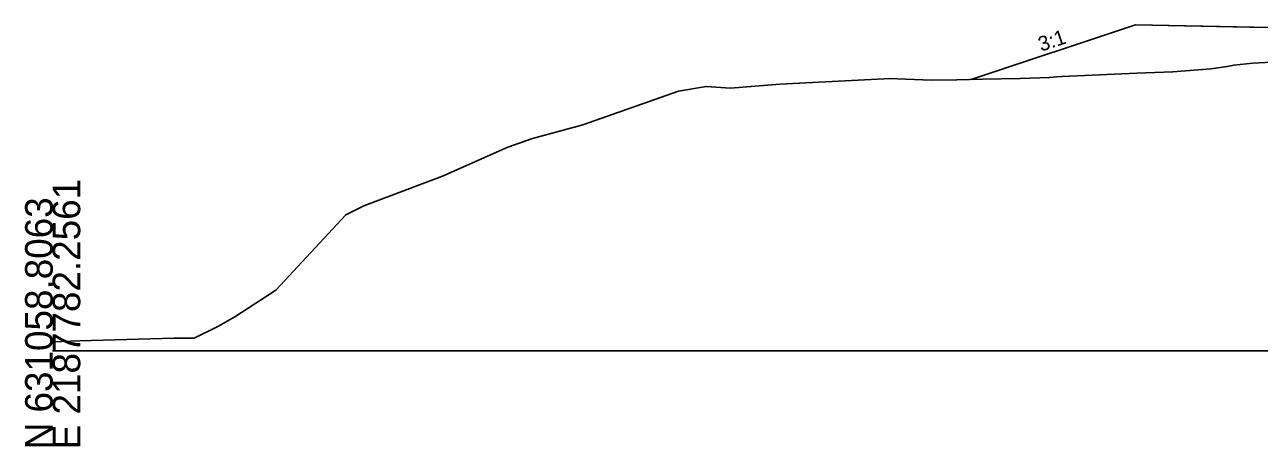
# Model space of a CAD drawing. Extents: x -26 to 4903, y -1010 to 9587.
# Drawn here: x 997.2 to 1122.6, y 7490.3 to 7533.1 of the extents above; entities that cross this region are included whole.
import ezdxf

# ---------------------------------------------------------------- set-up
doc = ezdxf.new("R2010")
doc.units = 0
for name, color, linetype in [('Default', 7, 'Continuous'), ('Exist Cross Section Cell', 7, 'Continuous'), ('Exist XS Ground Line', 7, 'Continuous'), ('Prop CMT Slope Grass', 7, 'Continuous'), ('Prop XS Earthwork Shape', 7, 'Continuous'), ('Prop XS Side Slope Text', 7, 'Continuous')]:
    doc.layers.add(name, color=color, linetype=linetype)

msp = doc.modelspace()

# ---------------------------------------------------------------- linework, layer by layer
at = {"layer": 'Exist Cross Section Cell'}
msp.add_line((1000, 7500), (1150, 7500), dxfattribs=at)
at = {"layer": 'Exist XS Ground Line'}
for p, q in [((1113.82, 7528.35), (1117.66, 7528.68)), ((1117.66, 7528.68), (1119.34, 7528.89)), ((1119.34, 7528.89), (1120.02, 7529.05)), ((1120.02, 7529.05), (1121.93, 7529.24)), ((1121.93, 7529.24), (1123.88, 7529.35)), ((1073.87, 7527.09), (1083.16, 7527.59)), ((1083.16, 7527.59), (1084.48, 7527.65)), ((1084.48, 7527.65), (1084.99, 7527.68)), ((1084.99, 7527.68), (1089.24, 7527.5)), ((1089.24, 7527.5), (1091.87, 7527.56)), ((1091.87, 7527.56), (1094.48, 7527.61)), ((1094.48, 7527.61), (1098.3, 7527.69)), ((1098.3, 7527.69), (1101.29, 7527.8)), ((1101.29, 7527.8), (1102.03, 7527.85)), ((1102.03, 7527.85), (1102.58, 7527.87)), ((1102.58, 7527.87), (1110.14, 7528.21)), ((1110.14, 7528.21), (1113.82, 7528.35)), ((1053.88, 7522.96), (1063.58, 7526.39)), ((1063.58, 7526.39), (1066.4, 7526.86)), ((1066.4, 7526.86), (1068.87, 7526.7)), ((1068.87, 7526.7), (1073.87, 7527.09)), ((1048.74, 7521.57), (1053.88, 7522.96)), ((1046.26, 7520.72), (1048.74, 7521.57)), ((1039.62, 7517.77), (1046.26, 7520.72)), ((1031.6, 7514.75), (1039.62, 7517.77)), ((1022.68, 7506.16), (1029.8, 7513.84)), ((1029.8, 7513.84), (1031.6, 7514.75)), ((1018.51, 7503.45), (1022.68, 7506.16)), ((1014.39, 7501.3), (1016.78, 7502.48)), ((1016.78, 7502.48), (1018.51, 7503.45)), ((1002.76, 7501.04), (1012.31, 7501.28)), ((1012.31, 7501.28), (1014.39, 7501.3)), ((1000, 7500.93), (1002.76, 7501.04))]:
    msp.add_line(p, q, dxfattribs=at)
at = {"layer": 'Prop CMT Slope Grass'}
for p, q in [((1110, 7533.15), (1093.33, 7527.59)), ((1125.5, 7532.84), (1110, 7533.15))]:
    msp.add_line(p, q, dxfattribs=at)
at = {"layer": 'Prop XS Earthwork Shape'}
msp.add_lwpolyline([(1123.26, 7532.88), (1110, 7533.15), (1093.33, 7527.59), (1094.48, 7527.61), (1098.3, 7527.69), (1101.29, 7527.8), (1102.03, 7527.85), (1102.58, 7527.87), (1110.14, 7528.21), (1113.82, 7528.35), (1117.66, 7528.68), (1119.34, 7528.89), (1120.02, 7529.05), (1121.93, 7529.24), (1123.88, 7529.35)], dxfattribs=at)

# ---------------------------------------------------------------- texts
at = {"layer": 'Default'}
msp.add_text('-', height=0.0001, dxfattribs=at).set_placement((1000, 7500))
at = {"layer": 'Exist Cross Section Cell'}
for s, p in [('E 2187782.2561', (1002.8, 7490)), ('N 631058.8063', (1000, 7490))]:
    msp.add_text(s, height=2.8, rotation=90, dxfattribs=at).set_placement(p)
at = {"layer": 'Prop XS Side Slope Text'}
msp.add_text('3:1', height=1.5, rotation=18.4349, dxfattribs=at).set_placement((1100.43, 7530.4))

doc.saveas('drawing.dxf')
